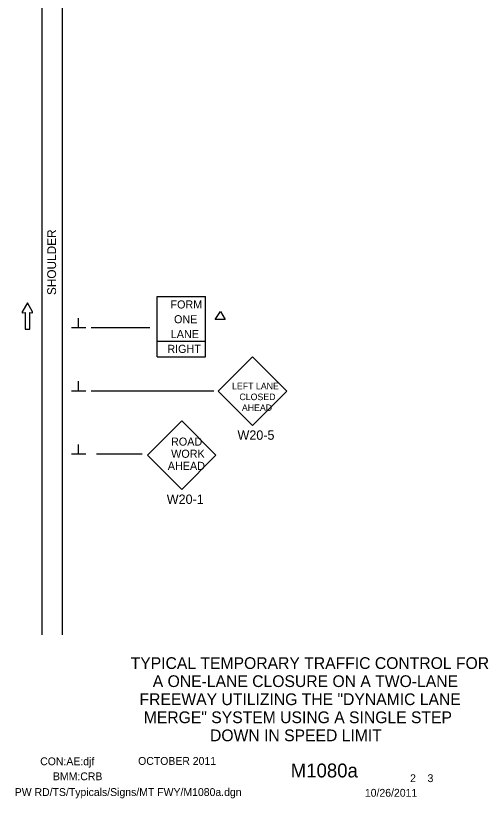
# Model space of a CAD drawing. Extents: x 15277 to 18126, y 1908 to 6555.
# Drawn here: x 16620 to 16994, y 2176 to 2796 of the extents above; entities that cross this region are included whole.
import ezdxf

# ---------------------------------------------------------------- set-up
doc = ezdxf.new("R2010")
doc.units = 0
for name, color, linetype in [('BORDER_SIGNAL_WO', 7, 'Continuous'), ('MT_SCRATCH_LEVEL_E', 7, 'Continuous'), ('PAVT_EDGE_EX', 7, 'Continuous'), ('TRAFFIC_SIGNS_PR', 7, 'Continuous'), ('TYPICAL_TEXT_DIMEN_PR', 7, 'Continuous')]:
    doc.layers.add(name, color=color, linetype=linetype)

msp = doc.modelspace()

# ---------------------------------------------------------------- linework, layer by layer
at = {"layer": 'MT_SCRATCH_LEVEL_E'}
for p, q in [((16628.88, 2568.38), (16624.77, 2561.14)), ((16633.03, 2561.14), (16628.88, 2568.38)), ((16625.25, 2560.45), (16627.03, 2560.77)), ((16627.03, 2560.77), (16627.03, 2547.51)), ((16630.77, 2547.51), (16630.77, 2560.77)), ((16630.77, 2560.77), (16632.55, 2560.45)), ((16627.03, 2547.51), (16630.77, 2547.51))]:
    msp.add_line(p, q, dxfattribs=at)
for centre, start, end in [((16625.17, 2560.91), 150.42484, 279.96381), ((16632.62, 2560.91), 260.03619, 29.77312)]:
    msp.add_arc(centre, 0.463, start, end, dxfattribs=at)
at = {"layer": 'PAVT_EDGE_EX'}
for p, q in [((16640.35, 3138.78), (16640.35, 2305.55)), ((16656.35, 3138.78), (16656.35, 2305.55))]:
    msp.add_line(p, q, dxfattribs=at)
at = {"layer": 'TRAFFIC_SIGNS_PR'}
for p, q in [((16731.73, 2525.54), (16731.73, 2573.5)), ((16731.73, 2573.5), (16770.1, 2573.5)), ((16770.1, 2525.54), (16770.1, 2573.5)), ((16731.73, 2537.95), (16770.1, 2537.95)), ((16731.73, 2525.54), (16770.1, 2525.54)), ((16807.18, 2525.7), (16780.03, 2498.55)), ((16834.33, 2498.55), (16807.18, 2525.7)), ((16780.03, 2498.55), (16807.18, 2471.4)), ((16807.18, 2471.4), (16834.33, 2498.55)), ((16751.15, 2474.94), (16724, 2447.79)), ((16778.3, 2447.79), (16751.15, 2474.94)), ((16724, 2447.79), (16751.15, 2420.64)), ((16751.15, 2420.64), (16778.3, 2447.79))]:
    msp.add_line(p, q, dxfattribs=at)
at = {"layer": 'TYPICAL_TEXT_DIMEN_PR'}
for p, q in [((16669.48, 2548.48), (16669.48, 2556.26)), ((16675.1, 2548.48), (16663.85, 2548.48)), ((16725.82, 2548.48), (16679.35, 2548.48)), ((16669.48, 2498.48), (16669.48, 2506.26)), ((16675.1, 2498.48), (16663.85, 2498.48)), ((16776.53, 2498.48), (16679.35, 2498.48)), ((16669.48, 2448.48), (16669.48, 2456.26)), ((16675.1, 2448.48), (16663.85, 2448.48)), ((16719.83, 2448.48), (16683.78, 2448.48))]:
    msp.add_line(p, q, dxfattribs=at)
msp.add_lwpolyline([(16777.6, 2555.15), (16781.97, 2561.45), (16785.67, 2555.15)], close=True, dxfattribs=at)

# ---------------------------------------------------------------- texts
at = {"layer": 'BORDER_SIGNAL_WO'}
for s, height, p in [('TYPICAL TEMPORARY TRAFFIC CONTROL FOR', 9.3, (16710.73, 2278.54)), ('A ONE-LANE CLOSURE ON A TWO-LANE', 9.3, (16728.24, 2264.24)), ('FREEWAY UTILIZING THE "DYNAMIC LANE', 9.3, (16717.74, 2249.94)), ('MERGE" SYSTEM USING A SINGLE STEP ', 9.3, (16721.1, 2235.64)), ('DOWN IN SPEED LIMIT', 9.3, (16773.6, 2221.34)), ('CON:AE:djf  ', 6.2, (16639.05, 2202.35)), ('    OCTOBER 2011    ', 6.2, (16707.44, 2202.63)), ('    M1080a   ', 11, (16821.22, 2192.67)), ('BMM:CRB   ', 6.2, (16649.17, 2190.46)), (' 2    3 ', 6.2, (16929.81, 2188.99)), ('PW RD/TS/Typicals/Signs/MT FWY/M1080a.dgn      ', 6.2, (16618.92, 2178)), ('10/26/2011    ', 6.2, (16896.29, 2177.42))]:
    msp.add_text(s, height=height, dxfattribs=at).set_placement(p)
at = {"layer": 'TRAFFIC_SIGNS_PR'}
for s, height, p in [('FORM', 6.394, (16742.26, 2563.91)), ('ONE', 6.394, (16745.07, 2552.19)), ('LANE', 6.394, (16742.49, 2540.47)), ('RIGHT', 6.394, (16739.78, 2528.74)), ('LEFT LANE', 5.2, (16791.06, 2499.94)), ('CLOSED', 5.2, (16796.89, 2491.34)), ('AHEAD', 5.2, (16798.84, 2482.74)), ('W20-5', 7.44, (16795.36, 2459.96)), ('ROAD', 6.4, (16742.69, 2455.32)), ('WORK', 6.4, (16742.8, 2445.72)), ('AHEAD', 6.4, (16740.11, 2436.12)), ('W20-1', 7.44, (16739.32, 2409.2))]:
    msp.add_text(s, height=height, dxfattribs=at).set_placement(p)
at = {"layer": 'TYPICAL_TEXT_DIMEN_PR'}
msp.add_text('SHOULDER', height=7, rotation=90, dxfattribs=at).set_placement((16651.63, 2574.49))

doc.saveas('drawing.dxf')
